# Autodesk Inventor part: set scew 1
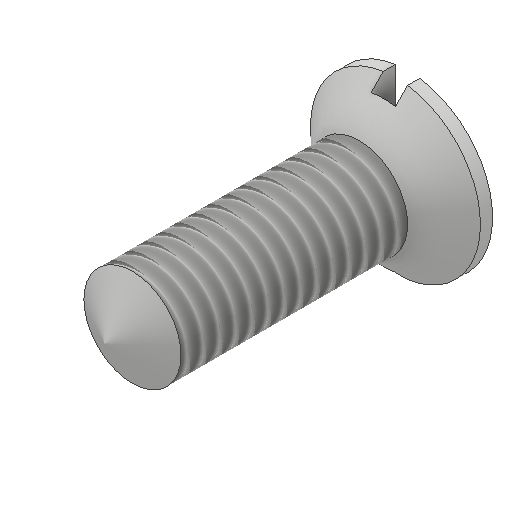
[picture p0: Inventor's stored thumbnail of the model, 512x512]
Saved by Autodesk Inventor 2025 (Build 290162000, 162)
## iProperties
Created: 2016-06
Part Number: set scew 1
Material: Generic
Document SubType Name: Modeling
Designer: CADCIM
Density: 1 g/cm^3
Appearance: Default
Mass: 0.577668 g
Surface Area: 5.12671 cm^2
Volume: 0.577668 cm^3
Author: CADCIM
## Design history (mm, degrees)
sketch "Sketch1"
  geometry: C1 r 3 at (0, 0); 1 further point
  constraints: 1 centre point, 1 coincident
  dimensions: "d0" = 6 diameter of C1
extrude "Extrusion1" new body sketch "Sketch1" distance "d1" = 14; taper "d2" = 0 deg
revolve "Revolution1" stored, may be unused: angle "d7" = 90 deg
sketch "Sketch3"
  geometry: C1 r 5.25 at (0, 0); 1 further point
  constraints: 1 centre point, 1 coincident
  dimensions: "d8" = 10.5 diameter of C1
extrude "Extrusion2" sketch "Sketch3" distance "d9" = 26.75; taper "d10" = 0 deg
sketch "Sketch4"
  geometry: L1 (-0.75, 8.347)-(0.75, 8.347); L2 (0.75, 8.347)-(0.75, -8.125); L3 (0.75, -8.125)-(-0.75, -8.125); L4 (-0.75, -8.125)-(-0.75, 8.347); L5 (0, 0)-(0, 6.165)
  constraints: 10 end point, 3 parallel, 1 horizontal, 1 perpendicular, 1 other
  dimensions: "d11" = 1.5 distance of L1.start L1.end
extrude "Extrusion3" cut sketch "Sketch4" distance "d12" = 1.5; taper "d13" = 0 deg
thread "Thread2" dims "d19" = 10, "d20" = 0
revolve "Revolution3" stored, may be unused: angle "d23" = 90 deg
body "Solid1"
sketch "Sketch5"
  geometry: L1 (0, 0)-(0, 3); L2 (0, 3)-(-1.732, 0); L3 (-1.732, 0)-(0, 0); L4 (0, 3)-(0, -3) reference; 1 further point
  constraints: 6 end point, 2 midpoint, 1 perpendicular, 1 point on line, 1 vertical
  dimensions: "d21" = 60 deg angle of L2 L3; "d22" = 3 distance of L1.start L1.end
sketch "Sketch2"
  geometry: L1 (14, -3)-(14, 3) reference; L2 (14, 0)-(14, -3); L3 (14, -3)-(17, -6); L4 (17, -6)-(17, 0); L5 (17, 0)-(14, 0); 1 further point
  constraints: 8 end point, 2 vertical, 1 midpoint, 1 perpendicular
  dimensions: "d4" = 3 distance of L2.start L2.end; "d5" = 6 distance of L4.end L3.end; "d6" = 3 distance from line of L1.start L4
